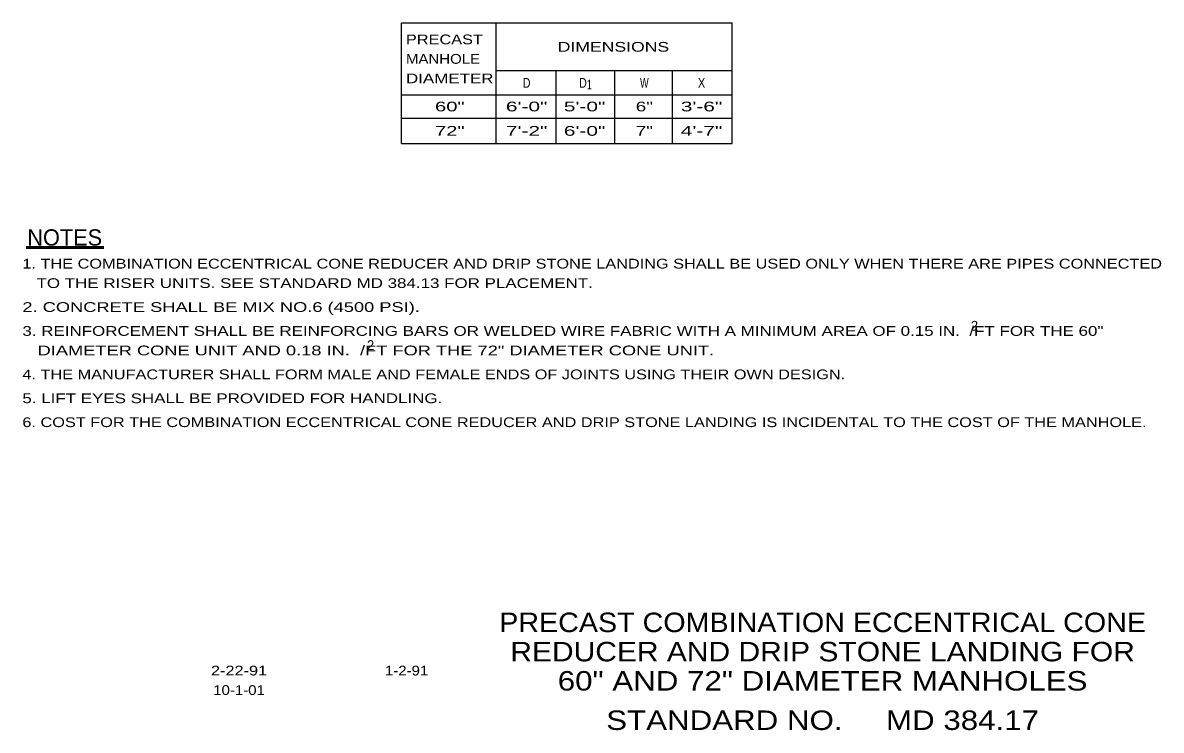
# Model space of a CAD drawing. Extents: x 5.1 to 20.2, y -16.7 to 4.3.
# Drawn here: x 5.12 to 20.19, y -16.66 to -7.3 of the extents above; entities that cross this region are included whole.
import ezdxf
from ezdxf.enums import TextEntityAlignment as Align

# ---------------------------------------------------------------- set-up
doc = ezdxf.new("R2010")
doc.units = 0
doc.header["$LTSCALE"] = 0.052
doc.layers.add('13', color=7, linetype='Continuous', lineweight=25)

msp = doc.modelspace()

# ---------------------------------------------------------------- linework, layer by layer
at = {"layer": '13'}
for p, q in [((10.13533, -7.29567), (14.51133, -7.29567)), ((10.13533, -8.89533), (10.13533, -7.29567)), ((11.38817, -8.89533), (11.38817, -7.29567)), ((14.51133, -8.89533), (14.51133, -7.29567)), ((14.51133, -7.93333), (11.38817, -7.93333)), ((12.181, -8.89533), (12.181, -7.93333)), ((12.9585, -8.89533), (12.9585, -7.93333)), ((13.72092, -8.89533), (13.72092, -7.93333)), ((10.1325, -8.24992), (14.51133, -8.24992)), ((10.13208, -8.55925), (14.51133, -8.55925)), ((10.13533, -8.89533), (14.51133, -8.89533))]:
    msp.add_line(p, q, dxfattribs=at)
at = {"layer": '13', "lineweight": 53}
msp.add_line((5.16767, -10.27267), (6.19508, -10.27267), dxfattribs=at)

# ---------------------------------------------------------------- texts
at = {"layer": '13'}
for s, width, p in [('PRECAST', 1.25, (10.19325, -7.58075)), ('MANHOLE', 1.15, (10.19325, -7.83875)), ('DIAMETER', 1.3, (10.19325, -8.09675)), ('1. THE COMBINATION ECCENTRICAL CONE REDUCER AND DRIP STONE LANDING SHALL BE USED ONLY WHEN THERE ARE PIPES CONNECTED', 1.25, (5.11625, -10.54992)), ('   TO THE RISER UNITS. SEE STANDARD MD 384.13 FOR PLACEMENT.', 1.3, (5.11625, -10.80792)), ('2. CONCRETE SHALL BE MIX NO.6 (4500 PSI).', 1.4, (5.11625, -11.12467)), ('3. REINFORCEMENT SHALL BE REINFORCING BARS OR WELDED WIRE FABRIC WITH A MINIMUM AREA OF 0.15 IN.  /FT FOR THE 60"', 1.3, (5.11625, -11.44133)), ('   DIAMETER CONE UNIT AND 0.18 IN.  /FT FOR THE 72" DIAMETER CONE UNIT.', 1.4, (5.11625, -11.69933)), ('4. THE MANUFACTURER SHALL FORM MALE AND FEMALE ENDS OF JOINTS USING THEIR OWN DESIGN.', 1.25, (5.11625, -12.01608)), ('5. LIFT EYES SHALL BE PROVIDED FOR HANDLING.', 1.3, (5.11625, -12.33283)), ('6. COST FOR THE COMBINATION ECCENTRICAL CONE REDUCER AND DRIP STONE LANDING IS INCIDENTAL TO THE COST OF THE MANHOLE.', 1.25, (5.11625, -12.64958))]:
    msp.add_text(s, height=0.129, dxfattribs=dict(at, width=width)).set_placement(p)
for s, height, width, p in [('DIMENSIONS', 0.129, 1.35, (12.93958, -7.679)), ('D', 0.129, 0.8, (11.79125, -8.15608)), ('D', 0.129, 0.8, (12.53708, -8.15608)), ('1', 0.129, 0.65, (12.62046, -8.17692)), ('W', 0.129, 0.7, (13.34875, -8.15608)), ('X', 0.129, 0.85, (14.10583, -8.15608)), ('60"', 0.129, 1.55, (10.77392, -8.46908)), ('6\'-0"', 0.129, 1.6, (11.79125, -8.46908)), ('5\'-0"', 0.129, 1.6, (12.55792, -8.46908)), ('6"', 0.129, 1.45, (13.34875, -8.46908)), ('3\'-6"', 0.129, 1.6, (14.10583, -8.46908)), ('72"', 0.129, 1.55, (10.77392, -8.79175)), ('7\'-2"', 0.129, 1.6, (11.79125, -8.79175)), ('6\'-0"', 0.129, 1.6, (12.55792, -8.79175)), ('7"', 0.129, 1.45, (13.34875, -8.79175)), ('4\'-7"', 0.129, 1.6, (14.10583, -8.79175)), ('PRECAST COMBINATION ECCENTRICAL CONE', 0.258, 1.1, (15.70812, -15.3645)), ('REDUCER AND DRIP STONE LANDING FOR', 0.258, 1.15, (15.70812, -15.7515)), ('2-22-91', 0.129, 1.25, (7.98379, -15.93842)), ('1-2-91', 0.129, 1.15, (10.20167, -15.93842)), ('60" AND 72" DIAMETER MANHOLES', 0.258, 1.2, (15.70812, -16.1385)), ('10-1-01', 0.129, 1.15, (7.98375, -16.19642)), ('STANDARD NO.     MD 384.17', 0.258, 1.2, (15.70808, -16.66017))]:
    msp.add_text(s, height=height, dxfattribs=dict(at, width=width)).set_placement(p, align=Align.CENTER)
msp.add_text('NOTES', height=0.215, dxfattribs=at).set_placement((5.67642, -10.24592), align=Align.CENTER)
for p in [(17.67092, -11.37242), (9.677, -11.62842)]:
    msp.add_text('2', height=0.129, dxfattribs=at).set_placement(p)

doc.saveas('drawing.dxf')
